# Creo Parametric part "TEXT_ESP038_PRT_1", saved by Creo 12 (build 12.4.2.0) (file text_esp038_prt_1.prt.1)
Units: Custom; MM, KILOGRAM, SECS

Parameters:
  PTC_WM_ITERATION = "0"
  PTC_WM_VERSION = "-.0"
  PTC_WM_LIFECYCLE_STATE = "In Work"
  PTC_WM_LIFECYCLE = "MO_CADDocument"
  PTC_WM_CREATED_BY = "Maximilian Roepper (Z0017RMS: MO)"
  PTC_WM_CREATED_ON = "18-Sep-26 11:36:42 AM"
  PTC_WM_MODIFIED_BY = "Maximilian Roepper (Z0017RMS: MO)"
  PTC_WM_MODIFIED_ON = "18-Sep-26 11:36:46 AM"
  PDMLINKNUMBER = "PDM000071455275"
  PTC_WM_NAME = "text_esp038_prt_1.prt"
  PTC_WM_NUMBER = "PDM000071455275"

Other parameters: WEIGHT, WEIGHT_FACTOR, WEIGHT_ADD, _MASS_TEMP, _DIFF_TEMP, MC_ERRORS, SUPPLIER

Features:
  1. coordinate system
  2. datum plane "PRT_YZ"
  3. datum plane "PRT_XY"
  4. datum plane "PRT_XZ"
  5. coordinate system
  6. datum axis
  7. datum axis
  8. datum axis
  9. coordinate system
  10. imported feature
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
Other named items: PRT, SIEMENS_MO, DRW_VIEW_ORG, PRT_X, PRT_Y, PRT_Z, CS0, ROUGH_GROB

Layers: 00_STD_CSYS-KSYS, 01_STD_PLANES-EBENEN, 02_STD_AXES-ACHSEN, 03_STD_CSYS-KSYS, 24_IMPORT_FEAT-IMPORT_KE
